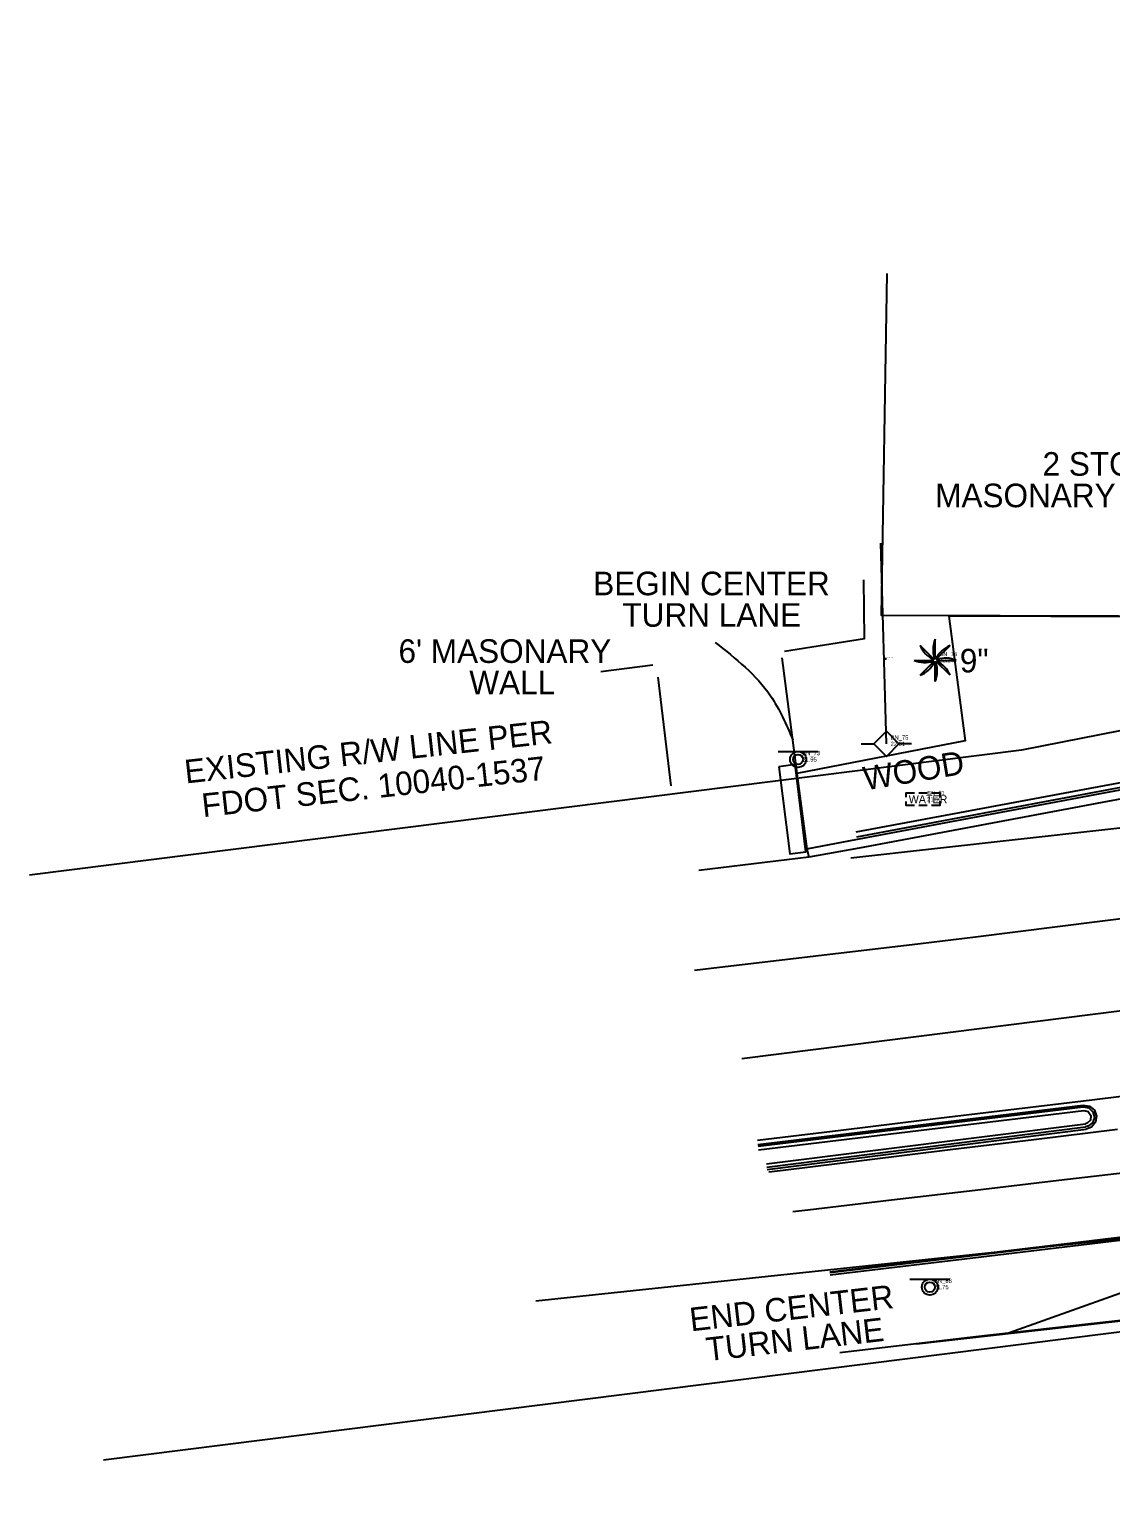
# Model space of a CAD drawing. Extents: x 509744 to 512285, y 1314862 to 1316822.
# Drawn here: x 510118.4 to 510246.7, y 1315900.5 to 1316076.2 of the extents above; entities that cross this region are included whole.
import ezdxf

# ---------------------------------------------------------------- set-up
doc = ezdxf.new("R2010")
doc.units = 0
for name, color, linetype in [('Building_ep', 7, 'Continuous'), ('CGBack_ep', 7, 'Continuous'), ('CGep_ep', 7, 'Continuous'), ('CGFace_ep', 7, 'Continuous'), ('CurbRampWarning_ep', 7, 'Continuous'), ('Driveway_ep', 7, 'Continuous'), ('ElecAer_ep', 7, 'Continuous'), ('GroundShot_ep', 7, 'Continuous'), ('LaneLine_ep', 7, 'Continuous'), ('MeterWater_ep', 7, 'Continuous'), ('PavtAsphalt_ep', 7, 'Continuous'), ('PavtAsphaltCrown_ep', 7, 'Continuous'), ('PMRK_ep', 7, 'Continuous'), ('PoleElec_ep', 7, 'Continuous'), ('RWLine_ep', 7, 'Continuous'), ('SidewalkBack_ep', 7, 'Continuous'), ('SignSingle_ep', 7, 'Continuous'), ('TextElevLabel', 7, 'Continuous'), ('TextNotes', 7, 'Continuous'), ('TextPtLabel', 7, 'Continuous'), ('TextTopoLabel_ep', 7, 'Continuous'), ('TextUtilLabel_ep', 7, 'Continuous'), ('TreePalm_ep', 7, 'Continuous'), ('Wall_ep', 7, 'Continuous')]:
    doc.layers.add(name, color=color, linetype=linetype)

msp = doc.modelspace()

# ---------------------------------------------------------------- linework, layer by layer
at = {"layer": 'Building_ep'}
for points in [[(510276.06, 1316044.05), (510275.85, 1316006.52), (510219.52, 1316006.68), (510220.21, 1316047.3)], [(510259.05, 1315851.85), (510276.05, 1315851.36), (510309.84, 1315866.32), (510305.24, 1315877.51), (510316.93, 1315882.94), (510320.96, 1315873.48), (510339.48, 1315881.39), (510339.66, 1315880.97), (510346.94, 1315884.01), (510342.75, 1315894.4), (510350.52, 1315897.68), (510351.47, 1315930.81), (510302.05, 1315929.61), (510275.85, 1315926.7), (510275.69, 1315926.17), (510273.59, 1315925.82), (510223.68, 1315920.2)]]:
    msp.add_lwpolyline(points, dxfattribs=at)
at = {"layer": 'CGBack_ep'}
msp.add_line((510205.88, 1315941.58), (510243.75, 1315946.36), dxfattribs=at)
for points in [[(510216.52, 1315980.99), (510246, 1315986.51), (510276.48, 1315992.18), (510279.62, 1315992.79), (510291.49, 1315995.02), (510294.58, 1315995.67), (510310.17, 1315998.65), (510313.24, 1315999.17), (510342.83, 1316004.57), (510346.91, 1316005.47), (510363.91, 1316008.77), (510368.6, 1316009.61), (510390.07, 1316013.48), (510393.38, 1316014.11), (510397.86, 1316014.85)], [(510204.94, 1315943.24), (510234.72, 1315946.87), (510243.55, 1315947.92)], [(510243.55, 1315947.92), (510244.09, 1315947.79), (510244.41, 1315947.34), (510244.36, 1315946.79), (510243.95, 1315946.41), (510243.75, 1315946.36)], [(510213.46, 1315928.41), (510229.38, 1315930.3), (510243.25, 1315931.97), (510273.03, 1315935.57), (510276.12, 1315936.03), (510276.38, 1315936.02), (510280.93, 1315936.71), (510302.09, 1315936.54), (510332.09, 1315936.33), (510348.1, 1315936.28), (510378.1, 1315936.11), (510408.1, 1315935.81), (510429.47, 1315935.61), (510437.55, 1315935.54), (510442.33, 1315934.9), (510445.5, 1315933.9), (510447.37, 1315932.97)]]:
    msp.add_lwpolyline(points, dxfattribs=at)
at = {"layer": 'CGep_ep'}
msp.add_lwpolyline([(510210.69, 1315978.98), (510216.68, 1315980.15), (510246.16, 1315985.67), (510276.63, 1315991.34)], dxfattribs=at)
at = {"layer": 'CGFace_ep'}
msp.add_line((510205.93, 1315941.2), (510243.76, 1315945.98), dxfattribs=at)
for points in [[(510216.62, 1315980.42), (510246.11, 1315985.97), (510276.57, 1315991.65), (510279.72, 1315992.24), (510291.59, 1315994.47), (510294.66, 1315995.2), (510310.27, 1315998.11), (510313.35, 1315998.63), (510342.93, 1316004.07), (510347, 1316005.01), (510363.99, 1316008.31), (510368.68, 1316009.15), (510390.15, 1316013.01), (510393.46, 1316013.64), (510397.94, 1316014.44)], [(510204.89, 1315943.69), (510234.67, 1315947.3), (510243.47, 1315948.35)], [(510243.47, 1315948.35), (510244.14, 1315948.24), (510244.64, 1315947.77), (510244.81, 1315947.11), (510244.58, 1315946.46), (510244.03, 1315946.05), (510243.76, 1315945.98)], [(510213.42, 1315928.71), (510229.34, 1315930.59), (510243.21, 1315932.27), (510272.99, 1315935.89), (510276.09, 1315936.35), (510276.34, 1315936.34), (510280.86, 1315937.07), (510302.09, 1315936.94), (510332.09, 1315936.74), (510348.11, 1315936.69), (510378.11, 1315936.52), (510408.1, 1315936.24), (510429.46, 1315936.03), (510437.55, 1315936.05), (510442.43, 1315935.37), (510445.59, 1315934.37), (510447.59, 1315933.43)]]:
    msp.add_lwpolyline(points, dxfattribs=at)
at = {"layer": 'CurbRampWarning_ep'}
msp.add_lwpolyline([(510207.36, 1315988.74), (510208.64, 1315978.39), (510210.55, 1315978.64), (510209.27, 1315988.98)], close=True, dxfattribs=at)
at = {"layer": 'Driveway_ep'}
msp.add_line((510193, 1315999.37), (510194.54, 1315986.46), dxfattribs=at)
for points in [[(510207.7, 1316001.68), (510209.5, 1315987.92)], [(510209.5, 1315987.92), (510210.69, 1315978.98), (510210.9, 1315978)]]:
    msp.add_lwpolyline(points, dxfattribs=at)
at = {"layer": 'ElecAer_ep'}
for p, q in [((510220.12, 1315991.45), (510219.47, 1316015.26)), ((510273.56, 1315935.37), (510234.72, 1315921.53))]:
    msp.add_line(p, q, dxfattribs=at)
msp.add_lwpolyline([(510525.11, 1315951.87), (510419.21, 1315935.43), (510273.56, 1315935.37), (510178.5, 1315925.31)], dxfattribs=at)
at = {"layer": 'GroundShot_ep'}
for p, q in [((510220.13, 1316001.53), (510219.88, 1316001.53)), ((510220, 1316001.41), (510220, 1316001.66))]:
    msp.add_line(p, q, dxfattribs=at)
at = {"layer": 'LaneLine_ep'}
msp.add_lwpolyline([(510415.4, 1315942.27), (510405.4, 1315942.42), (510395.4, 1315942.58), (510391.37, 1315942.64), (510381.37, 1315942.67), (510371.37, 1315942.71), (510361.37, 1315942.75), (510351.37, 1315942.79), (510341.37, 1315942.82), (510331.37, 1315942.86), (510321.37, 1315942.9), (510311.37, 1315942.93), (510301.37, 1315942.97), (510291.37, 1315943.01), (510281.37, 1315943.05), (510271.37, 1315943.08), (510270.39, 1315943.09), (510260.46, 1315941.93), (510250.53, 1315940.76), (510240.6, 1315939.6), (510230.66, 1315938.44), (510220.73, 1315937.28), (510210.8, 1315936.11), (510209.03, 1315935.91)], dxfattribs=at)
at = {"layer": 'MeterWater_ep'}
for points in [[(510222.46, 1315985.12), (510222.46, 1315985.62), (510223.46, 1315985.62)], [(510223.96, 1315985.62), (510224.96, 1315985.62)], [(510225.46, 1315985.62), (510226.46, 1315985.62), (510226.46, 1315985.12)], [(510223.46, 1315984.12), (510222.46, 1315984.12), (510222.46, 1315984.62)], [(510224.96, 1315984.12), (510223.96, 1315984.12)], [(510226.46, 1315984.62), (510226.46, 1315984.12), (510225.46, 1315984.12)]]:
    msp.add_lwpolyline(points, dxfattribs=at)
at = {"layer": 'PavtAsphalt_ep'}
msp.add_line((510205.96, 1315940.93), (510243.84, 1315945.71), dxfattribs=at)
for points in [[(510276.82, 1315990.27), (510246.37, 1315984.6), (510216.88, 1315979.08), (510210.9, 1315978), (510197.86, 1315976.42)], [(510204.87, 1315943.87), (510234.65, 1315947.49), (510243.49, 1315948.55)], [(510243.49, 1315948.55), (510244.23, 1315948.44), (510244.82, 1315947.97), (510245.08, 1315947.27), (510244.96, 1315946.53), (510244.48, 1315945.96), (510243.84, 1315945.71)], [(510213.42, 1315928.77), (510243.2, 1315932.33), (510272.99, 1315935.94), (510276.08, 1315936.4), (510276.16, 1315937.8), (510280.62, 1315938.43), (510302.1, 1315938.32), (510332.1, 1315938.15), (510348.12, 1315938.11), (510378.12, 1315937.93), (510408.12, 1315937.9), (510429.44, 1315937.69), (510437.53, 1315937.52), (510442.71, 1315936.74), (510445.88, 1315935.74), (510450.67, 1315933.45)]]:
    msp.add_lwpolyline(points, dxfattribs=at)
at = {"layer": 'PavtAsphaltCrown_ep'}
msp.add_lwpolyline([(510202.95, 1315954.11), (510227.75, 1315957.24), (510248.06, 1315959.79), (510256.17, 1315961.18)], dxfattribs=at)
at = {"layer": 'PMRK_ep'}
for points in [[(510215.88, 1315977.92), (510225.82, 1315979.04), (510235.76, 1315980.15), (510245.7, 1315981.26), (510255.63, 1315982.37)], [(510255.52, 1315971.62), (510230.71, 1315968.52), (510224.15, 1315967.7), (510199.32, 1315964.79), (510197.32, 1315964.56)], [(510204.8, 1315944.41), (510214.72, 1315945.61), (510224.65, 1315946.8), (510234.58, 1315948), (510244.51, 1315949.2), (510254.44, 1315950.4)], [(510247.55, 1315945.69), (510237.63, 1315944.46), (510227.7, 1315943.24), (510217.78, 1315942.02), (510207.85, 1315940.8), (510206.16, 1315940.59)]]:
    msp.add_lwpolyline(points, dxfattribs=at)
at = {"layer": 'PoleElec_ep'}
for p, q in [((510217.14, 1315991.45), (510218.64, 1315991.45)), ((510223.11, 1315991.45), (510221.61, 1315991.45))]:
    msp.add_line(p, q, dxfattribs=at)
msp.add_lwpolyline([(510218.64, 1315991.45), (510220.12, 1315992.94), (510221.61, 1315991.45), (510220.12, 1315989.96), (510218.64, 1315991.45)], dxfattribs=at)
at = {"layer": 'RWLine_ep'}
for points in [[(510461.56, 1316076.24), (510416.31, 1316026.13), (510236.18, 1315990.72), (510118.39, 1315975.87)], [(510318.07, 1315930.49), (510127.15, 1315906.42)]]:
    msp.add_lwpolyline(points, dxfattribs=at)
at = {"layer": 'SidewalkBack_ep'}
for points in [[(510275.91, 1316006.45), (510227.55, 1316006.59), (510229.46, 1315991.8), (510209.5, 1315987.92)], [(510214.6, 1315919.18), (510230.4, 1315921.05), (510244.39, 1315922.66), (510274.21, 1315925.96), (510275.64, 1315926.24), (510275.77, 1315926.76), (510277.25, 1315926.88), (510277.5, 1315926.91), (510282.58, 1315927.47), (510302.04, 1315929.66), (510332.05, 1315930.44), (510348.07, 1315930.81), (510378.06, 1315930.98), (510408.06, 1315930.84), (510429.52, 1315930.67)]]:
    msp.add_lwpolyline(points, dxfattribs=at)
at = {"layer": 'SignSingle_ep'}
for p, q in [((510207.25, 1315990.55), (510212, 1315990.55)), ((510222.9, 1315927.91), (510227.65, 1315927.91))]:
    msp.add_line(p, q, dxfattribs=at)
for centre, radius in [((510209.63, 1315989.6), 0.95), ((510209.63, 1315989.6), 0.594), ((510225.28, 1315926.96), 0.95), ((510225.28, 1315926.96), 0.594)]:
    msp.add_circle(centre, radius, dxfattribs=at)
at = {"layer": 'TextTopoLabel_ep'}
msp.add_spline([(510199.8, 1316003.5), (510206.35, 1315997.17), (510209, 1315991.94)], degree=3, dxfattribs=at)
at = {"layer": 'TreePalm_ep'}
for p, q in [((510225.73, 1316001.53), (510224.14, 1316003.12)), ((510225.91, 1316001.61), (510225.91, 1316003.86)), ((510226.08, 1316001.53), (510227.68, 1316003.12)), ((510223.41, 1316001.36), (510225.66, 1316001.36)), ((510224.14, 1315999.59), (510225.73, 1316001.18)), ((510225.91, 1315998.86), (510225.91, 1316001.11)), ((510227.68, 1315999.59), (510226.08, 1316001.18)), ((510226.16, 1316001.36), (510228.41, 1316001.36))]:
    msp.add_line(p, q, dxfattribs=at)
msp.add_circle((510225.91, 1316001.36), 0.25, dxfattribs=at)
for centre, start, end in [((510227.15, 1316004.36), 202.3801, 243.2114), ((510228.91, 1316002.61), 157.3801, 198.2114), ((510228.91, 1316000.12), 112.3801, 153.2114), ((510224.66, 1316004.36), 247.3801, 288.2114), ((510222.9, 1316002.59), 292.3801, 333.2114), ((510222.91, 1316000.11), 337.3801, 18.2114), ((510227.16, 1315998.36), 67.3801, 108.2114), ((510224.67, 1315998.35), 22.3801, 63.2114)]:
    msp.add_arc(centre, 3.25, start, end, dxfattribs=at)
at = {"layer": 'Wall_ep'}
msp.add_line((510186.2, 1316000.04), (510192.38, 1316000.84), dxfattribs=at)
msp.add_lwpolyline([(510208.03, 1316002.45), (510217.52, 1316003.97), (510217.43, 1316010.92)], dxfattribs=at)

# ---------------------------------------------------------------- texts
at = {"layer": 'MeterWater_ep'}
msp.add_text('WATER', height=0.95, dxfattribs=at).set_placement((510222.77, 1315984.4))
at = {"layer": 'TextElevLabel'}
for s, height, p in [('22.43', 0.1, (510220.1, 1316001.48)), ('22.24', 0.5, (510226.41, 1316001.11)), ('22.01', 0.5, (510220.62, 1315991.2)), ('21.95', 0.5, (510210.13, 1315989.35)), ('21.50', 0.5, (510224.96, 1315984.62)), ('21.75', 0.5, (510225.78, 1315926.71))]:
    msp.add_text(s, height=height, dxfattribs=at).set_placement(p)
at = {"layer": 'TextNotes'}
for s, p in [('EXISTING R/W LINE PER', (510136.94, 1315986.74)), ('FDOT SEC. 10040-1537', (510138.99, 1315982.74))]:
    msp.add_text(s, height=2.8, rotation=6.2659, dxfattribs=at).set_placement(p)
at = {"layer": 'TextPtLabel'}
for s, height, p in [('DEFAULT_1003', 0.1, (510220.1, 1316001.63)), ('BN_74', 0.5, (510226.41, 1316001.86)), ('BN_75', 0.5, (510220.62, 1315991.95)), ('BN_73', 0.5, (510210.13, 1315990.1)), ('BN_81', 0.5, (510224.96, 1315985.37)), ('BN_88', 0.5, (510225.78, 1315927.46))]:
    msp.add_text(s, height=height, dxfattribs=at).set_placement(p)
at = {"layer": 'TextTopoLabel_ep'}
for s, p in [('2 STORY', (510238.66, 1316023.28)), ('MASONARY BUILDING', (510225.91, 1316019.54)), ('BEGIN CENTER', (510185.31, 1316009.09)), ('TURN LANE', (510188.78, 1316005.35)), ("6' MASONARY ", (510162.19, 1316001.06)), ('9"', (510228.84, 1315999.93)), ('WALL', (510170.6, 1315997.32))]:
    msp.add_text(s, height=2.8, dxfattribs=at).set_placement(p)
for s, p in [('END CENTER', (510196.92, 1315921.7)), ('TURN LANE', (510198.87, 1315918.16))]:
    msp.add_text(s, height=2.8, rotation=6.5557, dxfattribs=at).set_placement(p)
at = {"layer": 'TextUtilLabel_ep'}
msp.add_text('WOOD', height=2.8, rotation=9.566, dxfattribs=at).set_placement((510217.63, 1315985.91))

doc.saveas('drawing.dxf')
